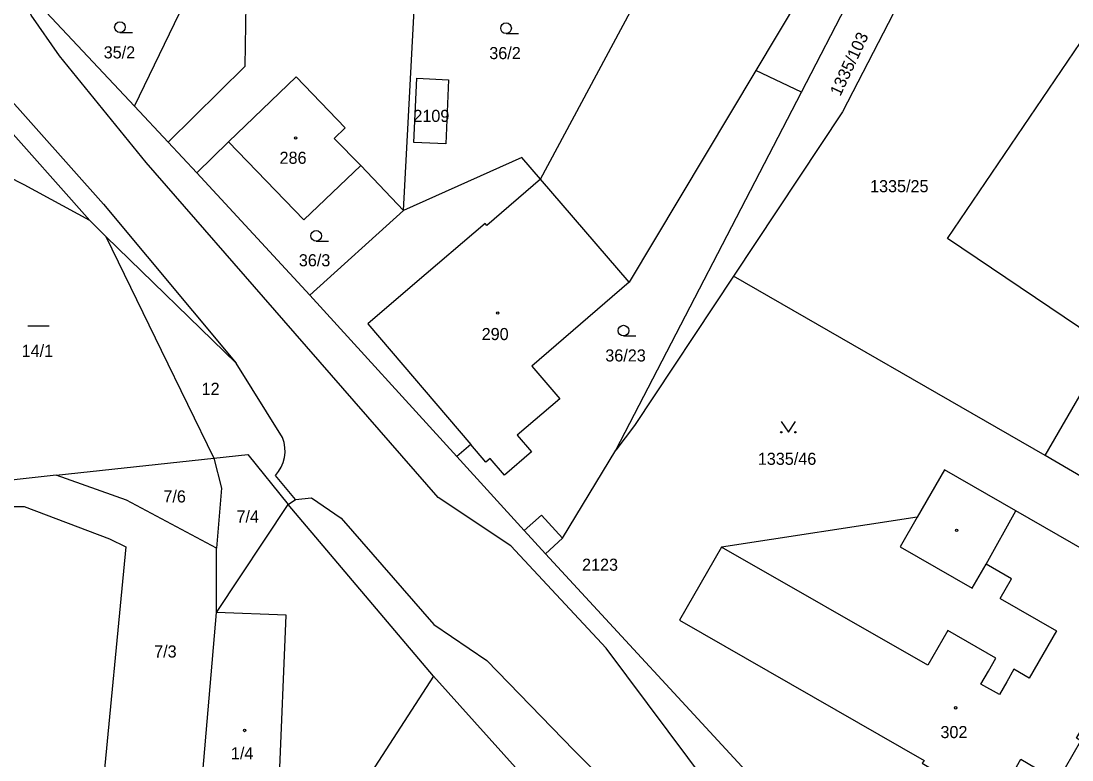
# Model space of a CAD drawing. Extents: x -793666 to -785424, y -1118958 to -1108761.
# Drawn here: x -788160.3 to -788012.6, y -1116813.7 to -1116709.8 of the extents above; entities that cross this region are included whole.
import ezdxf

# ---------------------------------------------------------------- set-up
doc = ezdxf.new("R2010")
doc.units = 0
for name, color, linetype in [('Hranice parcel', 7, 'Continuous'), ('Parcelní čísla', 7, 'Continuous'), ('Vnitřní kresba', 7, 'Continuous'), ('Značky budov', 7, 'Continuous'), ('Značky kultur', 7, 'Continuous')]:
    doc.layers.add(name, color=color, linetype=linetype)

msp = doc.modelspace()

# ---------------------------------------------------------------- linework, layer by layer
at = {"layer": 'Hranice parcel'}
for p, q in [((-788039.11, -1116686.8), (-788057.02, -1116716.71)), ((-788106.52, -1116736.42), (-788104.05, -1116689.18)), ((-788050.63, -1116719.77), (-788034.77, -1116689.16)), ((-788087.3, -1116732), (-788074.64, -1116708.43)), ((-788057.02, -1116716.71), (-788074.84, -1116746.49)), ((-788050.63, -1116719.77), (-788057.02, -1116716.71)), ((-788076.71, -1116770.1), (-788050.63, -1116719.77)), ((-788139.62, -1116726.8), (-788144.34, -1116721.76)), ((-788163.85, -1116722.94), (-788150.62, -1116737.84)), ((-788135.59, -1116731.14), (-788139.62, -1116726.8)), ((-788119.68, -1116748.33), (-788135.59, -1116731.14)), ((-788074.84, -1116746.49), (-788087.3, -1116732)), ((-788106.52, -1116736.42), (-788119.68, -1116748.33)), ((-788148.36, -1116740.05), (-788150.62, -1116737.84)), ((-788130.05, -1116757.89), (-788148.36, -1116740.05)), ((-788016.37, -1116770.88), (-788060.16, -1116745.63)), ((-788099.05, -1116770.99), (-788119.68, -1116748.33)), ((-788123.54, -1116768.33), (-788130.05, -1116757.89)), ((-788084.18, -1116782.46), (-788076.71, -1116770.1)), ((-788155.32, -1116773.64), (-788133.18, -1116771.22)), ((-788099.05, -1116770.99), (-788089.58, -1116781.39)), ((-787986.85, -1116788.1), (-788016.37, -1116770.88)), ((-788121.73, -1116777.04), (-788124.52, -1116773.68)), ((-788132.81, -1116792.93), (-788122.75, -1116777.73)), ((-788122.75, -1116777.73), (-788121.73, -1116777.04)), ((-788102.31, -1116801.86), (-788122.75, -1116777.73)), ((-788086.56, -1116784.66), (-788089.58, -1116781.39)), ((-788084.18, -1116782.46), (-788086.56, -1116784.66)), ((-788132.81, -1116792.93), (-788132.83, -1116783.9)), ((-788086.56, -1116784.66), (-788031.75, -1116844.15)), ((-788135.27, -1116821.65), (-788132.81, -1116792.93)), ((-788102.31, -1116801.86), (-788119.65, -1116828.64)), ((-788085.95, -1116820.1), (-788102.31, -1116801.86))]:
    msp.add_line(p, q, dxfattribs=at)
for points in [[(-788170.26, -1116598.58), (-788167.71, -1116612.57), (-788167.24, -1116621.25), (-788167.14, -1116639.36), (-788169.73, -1116678.01), (-788170.7, -1116698.04), (-788167.95, -1116708.86), (-788163.05, -1116719.36), (-788148.67, -1116735.52), (-788130.05, -1116757.89)], [(-787892.56, -1116976.99), (-787895.19, -1116981.23), (-787941.8, -1116937.65), (-788018.27, -1116866.79), (-788038.98, -1116846.21), (-788057.86, -1116825), (-788078.06, -1116797.96), (-788091.43, -1116783.54), (-788101.65, -1116776.74), (-788123.35, -1116751.89), (-788142.7, -1116729.68), (-788154.86, -1116714.68), (-788158.83, -1116708.96), (-788160.26, -1116705.12), (-788161.73, -1116697.18), (-788161.16, -1116678.39), (-788158.78, -1116640.39), (-788158.44, -1116620.71), (-788158.79, -1116611.56), (-788160.53, -1116602.53)], [(-788029.11, -1116692.03), (-788044.86, -1116722.53), (-788060.16, -1116745.63)], [(-788139.62, -1116726.8), (-788128.79, -1116716.13), (-788128.66, -1116707.4), (-788128.49, -1116696.22)], [(-788016.37, -1116770.88), (-788007.5, -1116755.59), (-788030.08, -1116740.37), (-788004.3, -1116702.25)], [(-788157.54, -1116707.2), (-788157.46, -1116707.77), (-788144.34, -1116721.76)], [(-788144.34, -1116721.76), (-788137.31, -1116707.2), (-788157.54, -1116707.2)], [(-788100.19, -1116718.04), (-788100.58, -1116727.03), (-788105.06, -1116726.84), (-788104.67, -1116717.83), (-788100.19, -1116718.04)], [(-788135.59, -1116731.14), (-788131.12, -1116726.76), (-788120.52, -1116737.71), (-788112.55, -1116730.09), (-788106.52, -1116736.42)], [(-788087.3, -1116732), (-788089.9, -1116728.97), (-788106.52, -1116736.42)], [(-788150.62, -1116737.84), (-788159.85, -1116732.8), (-788164.47, -1116730.47), (-788170.34, -1116730.13), (-788177.85, -1116736.6), (-788177.9, -1116738.22)], [(-788148.36, -1116740.05), (-788140.56, -1116756.06), (-788133.18, -1116771.22)], [(-788060.16, -1116745.63), (-788074.07, -1116766.64), (-788076.71, -1116770.1)], [(-788074.84, -1116746.49), (-788088.51, -1116758.3), (-788084.57, -1116762.91), (-788090.55, -1116768.01), (-788088.54, -1116770.36), (-788092.35, -1116773.62), (-788094.36, -1116771.26), (-788094.97, -1116771.78), (-788097.08, -1116769.3), (-788099.05, -1116770.99)], [(-788124.52, -1116773.68), (-788124.08, -1116773.12), (-788123.71, -1116772.5), (-788123.44, -1116771.84), (-788123.26, -1116771.15), (-788123.18, -1116770.43), (-788123.2, -1116769.72), (-788123.32, -1116769.01), (-788123.54, -1116768.33)], [(-788133.18, -1116771.22), (-788128.42, -1116770.7), (-788122.75, -1116777.73)], [(-788133.18, -1116771.22), (-788132.1, -1116775.46), (-788132.83, -1116783.9)], [(-788155.32, -1116773.64), (-788166.71, -1116774.89), (-788168.7, -1116775.11)], [(-788132.83, -1116783.9), (-788145.44, -1116777.13), (-788155.32, -1116773.64)], [(-788067.75, -1116794.03), (-788033.39, -1116813.75), (-788033.67, -1116814.13), (-788027.08, -1116818.05), (-788023.52, -1116820.1), (-788021.63, -1116816.78), (-788019.77, -1116813.56), (-788015.67, -1116816), (-788014.58, -1116816.6), (-788011.36, -1116810.96), (-788011.98, -1116810.6), (-788004.49, -1116797.7), (-788002.85, -1116798.65), (-787998.57, -1116791.26), (-788020.48, -1116778.64), (-788030.53, -1116772.85), (-788034.34, -1116779.51), (-788061.85, -1116783.73), (-788067.75, -1116794.03)], [(-788168.06, -1116778.04), (-788159.81, -1116778.04), (-788147.84, -1116782.59), (-788145.53, -1116783.68), (-788148.95, -1116819.33)], [(-788121.73, -1116777.04), (-788119.47, -1116776.79), (-788115.27, -1116779.69), (-788102.26, -1116794.62), (-788094.84, -1116799.67), (-788082.62, -1116812.27), (-788064.51, -1116830.39), (-788036.35, -1116859.97), (-788022.19, -1116874.41)], [(-788089.58, -1116781.39), (-788087.13, -1116779.24), (-788084.18, -1116782.46)]]:
    msp.add_lwpolyline(points, dxfattribs=at)
at = {"layer": 'Vnitřní kresba'}
for p, q in [((-788121.63, -1116717.62), (-788131.12, -1116726.76)), ((-788114.73, -1116724.78), (-788121.63, -1116717.62)), ((-788116.28, -1116726.27), (-788114.73, -1116724.78)), ((-788112.55, -1116730.09), (-788116.28, -1116726.27)), ((-788087.3, -1116732), (-788094.81, -1116738.52)), ((-788095.06, -1116738.23), (-788104.92, -1116746.67)), ((-788094.81, -1116738.52), (-788095.06, -1116738.23)), ((-788104.92, -1116746.67), (-788111.55, -1116752.35)), ((-788111.55, -1116752.35), (-788097.08, -1116769.3)), ((-788034.34, -1116779.51), (-788036.73, -1116783.69)), ((-788024.68, -1116786.13), (-788020.48, -1116778.64)), ((-788032.86, -1116800.34), (-788061.85, -1116783.73)), ((-788036.73, -1116783.69), (-788026.62, -1116789.5)), ((-788026.62, -1116789.5), (-788024.68, -1116786.13)), ((-788021.12, -1116788.18), (-788024.68, -1116786.13)), ((-788022.71, -1116790.94), (-788021.12, -1116788.18)), ((-788022.71, -1116790.94), (-788014.77, -1116795.51)), ((-788123.03, -1116793.32), (-788132.81, -1116792.93)), ((-788124.43, -1116828.22), (-788123.03, -1116793.32)), ((-788030.06, -1116795.48), (-788032.86, -1116800.34)), ((-788023.31, -1116799.36), (-788030.06, -1116795.48)), ((-788014.77, -1116795.51), (-788018.61, -1116802.16)), ((-788024.35, -1116801.17), (-788023.31, -1116799.36)), ((-788025.4, -1116802.99), (-788024.35, -1116801.17)), ((-788020.76, -1116800.92), (-788021.76, -1116802.66)), ((-788018.61, -1116802.16), (-788020.76, -1116800.92)), ((-788022.8, -1116804.48), (-788025.4, -1116802.99)), ((-788021.76, -1116802.66), (-788022.8, -1116804.48))]:
    msp.add_line(p, q, dxfattribs=at)
at = {"layer": 'Značky budov'}
for centre in [(-788121.69, -1116726.21), (-788093.29, -1116750.83), (-788028.82, -1116781.38), (-788028.96, -1116806.34), (-788128.86, -1116809.51)]:
    msp.add_circle(centre, 0.175, dxfattribs=at)
at = {"layer": 'Značky kultur'}
for p, q in [((-788146.37, -1116711.39), (-788144.62, -1116711.39)), ((-788092.12, -1116711.54), (-788090.37, -1116711.54)), ((-788118.81, -1116740.72), (-788117.06, -1116740.72)), ((-788159.31, -1116752.65), (-788156.31, -1116752.65)), ((-788075.62, -1116754.05), (-788073.87, -1116754.05))]:
    msp.add_line(p, q, dxfattribs=at)
msp.add_lwpolyline([(-788053.46, -1116766.08), (-788052.46, -1116767.58), (-788051.46, -1116766.08)], dxfattribs=at)
for centre, radius in [((-788146.37, -1116710.64), 0.75), ((-788092.12, -1116710.79), 0.75), ((-788118.81, -1116739.97), 0.75), ((-788075.62, -1116753.3), 0.75), ((-788053.46, -1116767.58), 0.1), ((-788051.46, -1116767.58), 0.1)]:
    msp.add_circle(centre, radius, dxfattribs=at)

# ---------------------------------------------------------------- texts
at = {"layer": 'Parcelní čísla'}
msp.add_text('1335/103', height=1.7, rotation=65, dxfattribs=at).set_placement((-788045.16, -1116720.45))
for s, p in [('35/2', (-788148.66, -1116715.03)), ('36/2', (-788094.48, -1116715.13)), ('2109', (-788105.15, -1116723.96)), ('286', (-788123.95, -1116729.85)), ('1335/25', (-788040.98, -1116733.84)), ('36/3', (-788121.24, -1116744.26)), ('290', (-788095.55, -1116754.63)), ('14/1', (-788160.19, -1116756.99)), ('36/23', (-788078.18, -1116757.64)), ('12', (-788134.9, -1116762.33)), ('1335/46', (-788056.75, -1116772.17)), ('7/6', (-788140.27, -1116777.46)), ('7/4', (-788130, -1116780.29)), ('2123', (-788081.45, -1116787.06)), ('7/3', (-788141.57, -1116799.26)), ('302', (-788031.09, -1116810.59)), ('1/4', (-788130.78, -1116813.57))]:
    msp.add_text(s, height=1.7, dxfattribs=at).set_placement(p)

doc.saveas('drawing.dxf')
